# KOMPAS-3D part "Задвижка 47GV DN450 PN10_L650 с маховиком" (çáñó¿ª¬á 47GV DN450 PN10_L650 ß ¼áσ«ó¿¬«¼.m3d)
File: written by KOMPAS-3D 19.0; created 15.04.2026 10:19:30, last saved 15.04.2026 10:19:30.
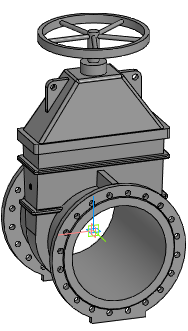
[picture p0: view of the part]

Document properties: Автор: Евгений; Полное имя файла: Z:\3.Личные\kachalov\3d для проектировщиков\2.1 Тип 47GV, 47GV.Z\Задвижка 47GV_DN40-DN600\stp_Задвижка 47GV\Задвижка 47GV DN450 PN10_L650 с маховиком.m3d

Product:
- Part/product: Задвижка 47GV DN450 PN10_L650 с маховиком

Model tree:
1. Операция без истории:1  (labels: Задвижка 47GV DN450 PN10_L650 с маховиком)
